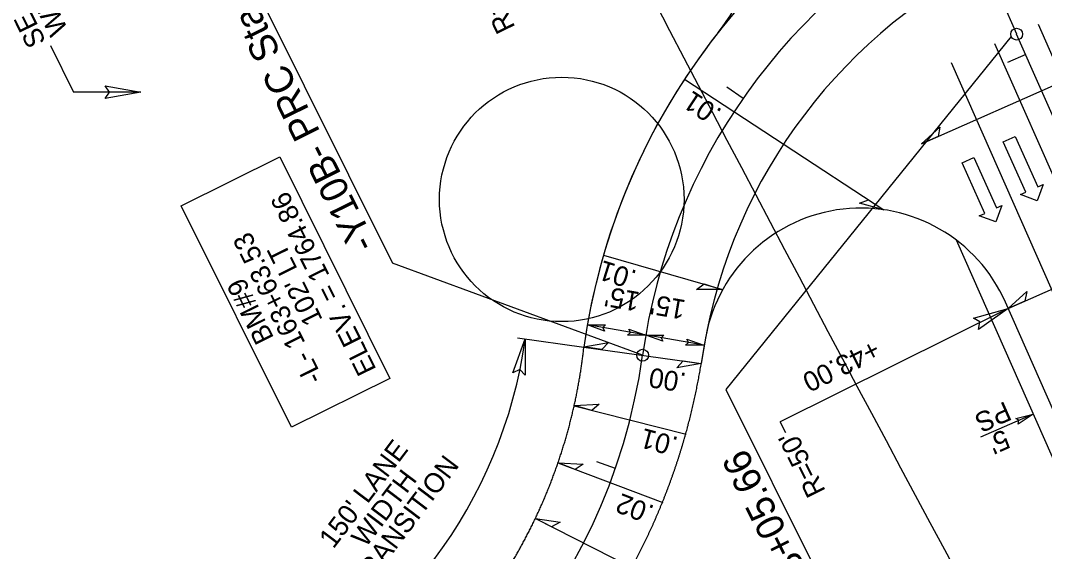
# Model space of a CAD drawing. Extents: x 472216 to 481979, y 489069 to 507339.
# Drawn here: x 475503.5 to 475762.8, y 502065.2 to 502199.7 of the extents above; entities that cross this region are included whole.
import ezdxf

# ---------------------------------------------------------------- set-up
doc = ezdxf.new("R2010")
doc.units = 0
for name, color, linetype in [('Exist Horizontal Alignment Point', 7, 'Continuous'), ('Old_Level_12', 7, 'Continuous'), ('Prop Drainage Structure Drop Inlet Grate 2 Narrow Slots and Sag Grates 840 24 CELL', 7, 'Continuous'), ('Prop Drainage Structure Drop Inlet Grate 2 Wide Slots and Sag Grates 840 22 Label', 7, 'Continuous'), ('Prop Drainage Structure Outlet Berm Ditch 850 10 CELL', 7, 'Continuous'), ('Prop Drainage Structure Pipe CSP 15in', 7, 'Continuous'), ('Prop Drainage Structure Pipe RCP 15in Class III Label', 7, 'Continuous'), ('Prop Drainage Structure Pipe RCP 24in Class III Label', 7, 'Continuous'), ('Prop Drainage Structure Pipe Side Drain 15in Label', 7, 'Continuous'), ('Prop Erosion Embankment Toe Protection CELL', 7, 'Continuous'), ('Prop Erosion Embankment Toe Protection Label', 7, 'Continuous'), ('Sheet Block Revision CELL', 7, 'Continuous'), ('Sheet North Arrow Point CELL', 7, 'Continuous'), ('Sheet PE Seal Cell', 7, 'Continuous'), ('Sheet Plot Border Outside CELL', 7, 'Continuous')]:
    doc.layers.add(name, color=color, linetype=linetype)

msp = doc.modelspace()

# ---------------------------------------------------------------- linework, layer by layer
at = {"layer": 'Exist Horizontal Alignment Point'}
msp.add_lwpolyline([(475572.15, 502096.69), (475544.25, 502152.79), (475569.16, 502165.18), (475597.06, 502109.08)], close=True, dxfattribs=at)
at = {"layer": 'Old_Level_12'}
for p, q in [((475538.53, 502257.18), (475597.67, 502138.26)), ((475754.34, 502195.64), (475682.12, 502106.24)), ((475661.02, 502114.94), (475597.67, 502138.26)), ((475682.12, 502106.24), (475733.03, 502003.86))]:
    msp.add_line(p, q, dxfattribs=at)
for centre in [(475755.71, 502196.25), (475755.71, 502196.25), (475755.71, 502196.25), (475661.02, 502114.94)]:
    msp.add_circle(centre, 1.5, dxfattribs=at)
at = {"layer": 'Prop Drainage Structure Drop Inlet Grate 2 Narrow Slots and Sag Grates 840 24 CELL'}
for points in [[(475731.6, 502168.47), (475736.28, 502172.73), (475735.83, 502170.34)], [(475722.06, 502151.79), (475715.95, 502153.41), (475718.2, 502154.33)], [(475680.96, 502131.55), (475674.64, 502131.55), (475676.57, 502133.01)], [(475753.57, 502126.8), (475758.26, 502131.05), (475757.81, 502128.67)], [(475646.17, 502117.07), (475652.41, 502118.13), (475650.74, 502116.36)], [(475675.88, 502112.88), (475669.66, 502111.73), (475671.3, 502113.52)], [(475643.71, 502102.18), (475650.02, 502102.56), (475648.17, 502100.99)], [(475639.63, 502087.73), (475645.94, 502087.4), (475643.93, 502086.04)], [(475633.87, 502073.6), (475640.12, 502072.67), (475638, 502071.51)]]:
    msp.add_lwpolyline(points, close=True, dxfattribs=at)
at = {"layer": 'Prop Drainage Structure Drop Inlet Grate 2 Wide Slots and Sag Grates 840 22 Label'}
for p, q in [((475731.6, 502168.47), (475789.07, 502193.84)), ((475671.65, 502184.87), (475722.06, 502151.79)), ((475753.57, 502126.8), (475806.17, 502150.02)), ((475651.13, 502140.29), (475681.28, 502131.55)), ((475646.16, 502117), (475675.88, 502112.88)), ((475643.69, 502102.11), (475672.01, 502094.99)), ((475639.6, 502087.67), (475666.18, 502077.67)), ((475633.87, 502073.6), (475658.26, 502061.15))]:
    msp.add_line(p, q, dxfattribs=at)
at = {"layer": 'Prop Drainage Structure Outlet Berm Ditch 850 10 CELL'}
for points in [[(475524.99, 502183.14), (475534, 502181.6), (475524.95, 502179.99), (475526.1, 502181.59)], [(475744.75, 502124.33), (475753.54, 502126.8), (475746.06, 502121.46), (475746.41, 502123.4)], [(475651.34, 502121.07), (475647.04, 502122.61), (475651.63, 502122.62), (475650.93, 502121.93)], [(475657.51, 502121.54), (475661.81, 502120), (475657.22, 502119.99), (475657.92, 502120.68)], [(475628.2, 502110.48), (475631.3, 502119.06), (475631.29, 502109.87), (475629.91, 502111.29)], [(475666.11, 502118.47), (475661.81, 502120), (475666.41, 502120.01), (475665.71, 502119.32)], [(475672.21, 502119.02), (475676.51, 502117.48), (475671.91, 502117.47), (475672.62, 502118.16)], [(475755.48, 502098.95), (475759.91, 502100.06), (475756.1, 502097.5), (475756.3, 502098.46)]]:
    msp.add_lwpolyline(points, close=True, dxfattribs=at)
at = {"layer": 'Prop Drainage Structure Pipe RCP 15in Class III Label'}
for p, q in [((476004.65, 501647.13), (475761.2, 502198.67)), ((475993.67, 501642.28), (475750.22, 502193.82))]:
    msp.add_line(p, q, dxfattribs=at)
at = {"layer": 'Prop Drainage Structure Pipe RCP 24in Class III Label'}
for p, q in [((475830.54, 501952.44), (475752.89, 502128.36)), ((475677.01, 502119.73), (475675.88, 502112.88))]:
    msp.add_line(p, q, dxfattribs=at)
for centre, radius, start, end in [((475640.96, 502227.71), 50, 321.6636, 23.3554), ((475809.6, 502094.35), 165, 141.6636, 172.1099), ((475716.29, 502112.21), 40, 23.8164, 169.165)]:
    msp.add_arc(centre, radius, start, end, dxfattribs=at)
for points in [[(475633.52, 502072.87), (475633.79, 502073.44), (475634.06, 502074), (475634.32, 502074.57), (475634.59, 502075.14), (475634.85, 502075.71), (475635.1, 502076.28), (475635.36, 502076.85), (475635.61, 502077.42), (475635.86, 502078), (475636.11, 502078.57), (475636.35, 502079.15), (475636.59, 502079.72), (475636.83, 502080.3), (475637.07, 502080.88), (475637.3, 502081.46), (475637.53, 502082.04), (475637.76, 502082.62), (475637.98, 502083.21), (475638.2, 502083.79), (475638.42, 502084.38), (475638.64, 502084.96), (475638.85, 502085.55), (475639.07, 502086.14), (475639.27, 502086.73), (475639.48, 502087.31), (475639.68, 502087.9), (475639.88, 502088.5), (475640.08, 502089.09), (475640.28, 502089.68), (475640.47, 502090.27), (475640.66, 502090.87), (475640.85, 502091.46), (475641.03, 502092.06), (475641.21, 502092.66), (475641.39, 502093.25), (475641.56, 502093.85), (475641.74, 502094.45), (475641.91, 502095.05), (475642.07, 502095.65), (475642.24, 502096.25), (475642.4, 502096.85), (475642.56, 502097.46), (475642.72, 502098.06), (475642.87, 502098.66), (475643.02, 502099.27), (475643.17, 502099.87), (475643.31, 502100.48), (475643.46, 502101.08), (475643.59, 502101.69), (475643.73, 502102.3), (475643.86, 502102.9), (475644, 502103.51), (475644.12, 502104.12), (475644.25, 502104.73), (475644.37, 502105.34), (475644.49, 502105.95), (475644.61, 502106.56), (475644.72, 502107.17), (475644.83, 502107.78), (475644.94, 502108.39), (475645.05, 502109.01), (475645.15, 502109.62), (475645.25, 502110.23), (475645.35, 502110.85), (475645.44, 502111.46), (475645.53, 502112.07), (475645.62, 502112.69), (475645.71, 502113.3), (475645.79, 502113.92), (475645.87, 502114.53), (475645.95, 502115.15), (475646.02, 502115.77), (475646.16, 502117)], [(475657.8, 502060.31), (475658.16, 502060.97), (475658.51, 502061.63), (475658.87, 502062.29), (475659.22, 502062.96), (475659.57, 502063.63), (475659.91, 502064.3), (475660.25, 502064.97), (475660.59, 502065.64), (475660.93, 502066.31), (475661.26, 502066.99), (475661.59, 502067.66), (475661.92, 502068.34), (475662.24, 502069.02), (475662.56, 502069.7), (475662.88, 502070.38), (475663.19, 502071.07), (475663.5, 502071.76), (475663.81, 502072.44), (475664.12, 502073.13), (475664.42, 502073.82), (475664.72, 502074.51), (475665.01, 502075.21), (475665.3, 502075.9), (475665.59, 502076.6), (475665.88, 502077.3), (475666.16, 502077.99), (475666.44, 502078.7), (475666.72, 502079.4), (475666.99, 502080.1), (475667.26, 502080.8), (475667.53, 502081.51), (475667.79, 502082.22), (475668.05, 502082.93), (475668.31, 502083.63), (475668.56, 502084.35), (475668.81, 502085.06), (475669.06, 502085.77), (475669.3, 502086.48), (475669.54, 502087.2), (475669.78, 502087.92), (475670.02, 502088.64), (475670.25, 502089.35), (475670.47, 502090.07), (475670.7, 502090.8), (475670.92, 502091.52), (475671.14, 502092.24), (475671.35, 502092.97), (475671.56, 502093.69), (475671.77, 502094.42), (475671.98, 502095.15), (475672.18, 502095.88), (475672.37, 502096.6), (475672.57, 502097.34), (475672.76, 502098.07), (475672.95, 502098.8), (475673.13, 502099.53), (475673.31, 502100.27), (475673.49, 502101), (475673.67, 502101.74), (475673.84, 502102.48), (475674.01, 502103.21), (475674.17, 502103.95), (475674.33, 502104.69), (475674.49, 502105.43), (475674.64, 502106.18), (475674.79, 502106.92), (475674.94, 502107.66), (475675.09, 502108.4), (475675.23, 502109.15), (475675.36, 502109.89), (475675.5, 502110.64), (475675.63, 502111.39), (475675.88, 502112.88)], [(475606.62, 502035.12), (475607.07, 502035.57), (475607.52, 502036.02), (475607.96, 502036.47), (475608.4, 502036.92), (475608.84, 502037.38), (475609.28, 502037.83), (475609.71, 502038.29), (475610.14, 502038.75), (475610.57, 502039.21), (475611, 502039.68), (475611.43, 502040.14), (475611.85, 502040.61), (475612.28, 502041.08), (475612.69, 502041.55), (475613.11, 502042.03), (475613.53, 502042.5), (475613.94, 502042.98), (475614.35, 502043.46), (475614.76, 502043.94), (475615.16, 502044.42), (475615.57, 502044.91), (475615.97, 502045.39), (475616.37, 502045.88), (475616.77, 502046.37), (475617.16, 502046.86), (475617.55, 502047.36), (475617.94, 502047.85), (475618.33, 502048.35), (475618.72, 502048.85), (475619.1, 502049.35), (475619.48, 502049.85), (475619.86, 502050.35), (475620.23, 502050.86), (475620.61, 502051.37), (475620.98, 502051.87), (475621.35, 502052.38), (475621.71, 502052.9), (475622.08, 502053.41), (475622.44, 502053.93), (475622.8, 502054.44), (475623.15, 502054.96), (475623.51, 502055.48), (475623.86, 502056), (475624.21, 502056.52), (475624.56, 502057.05), (475624.9, 502057.57), (475625.24, 502058.1), (475625.58, 502058.63), (475625.92, 502059.16), (475626.25, 502059.69), (475626.59, 502060.23), (475626.92, 502060.76), (475627.24, 502061.3), (475627.57, 502061.84), (475627.89, 502062.37), (475628.21, 502062.92), (475628.53, 502063.46), (475628.84, 502064), (475629.15, 502064.55), (475629.46, 502065.09), (475629.77, 502065.64), (475630.07, 502066.19), (475630.37, 502066.74), (475630.67, 502067.29), (475630.97, 502067.84), (475631.26, 502068.4), (475631.55, 502068.95), (475631.84, 502069.51), (475632.13, 502070.06), (475632.41, 502070.62), (475632.69, 502071.18), (475632.97, 502071.75), (475633.25, 502072.31), (475633.52, 502072.87)]]:
    msp.add_spline(points, degree=3, dxfattribs=at)
at = {"layer": 'Prop Drainage Structure Pipe Side Drain 15in Label'}
for p, q in [((475752.32, 502168.99), (475755.32, 502170.35)), ((475758.07, 502156.23), (475752.32, 502168.99)), ((475755.32, 502170.35), (475761.08, 502157.58)), ((475741.88, 502163.64), (475744.88, 502164.99)), ((475747.63, 502150.87), (475741.88, 502163.64)), ((475744.88, 502164.99), (475750.64, 502152.23)), ((475762.44, 502158.2), (475760.91, 502154.06)), ((475761.08, 502157.58), (475762.44, 502158.2)), ((475756.7, 502155.61), (475758.07, 502156.23)), ((475760.91, 502154.06), (475756.7, 502155.61)), ((475752, 502152.85), (475750.47, 502148.7)), ((475750.64, 502152.23), (475752, 502152.85)), ((475746.26, 502150.26), (475747.63, 502150.87)), ((475750.47, 502148.7), (475746.26, 502150.26))]:
    msp.add_line(p, q, dxfattribs=at)
at = {"layer": 'Prop Erosion Embankment Toe Protection CELL'}
msp.add_line((475829.51, 501942.39), (475740.49, 502144.06), dxfattribs=at)
at = {"layer": 'Prop Erosion Embankment Toe Protection Label'}
for p, q in [((475982.69, 501637.44), (475739.25, 502188.98)), ((475697.29, 502095.27), (475695.88, 502098.11))]:
    msp.add_line(p, q, dxfattribs=at)
at = {"layer": 'Sheet Block Revision CELL'}
for p, q in [((475511.1, 502193.41), (475517, 502181.55)), ((475753.57, 502126.8), (475695.88, 502098.11)), ((475676.59, 502117.47), (475647.04, 502122.61)), ((475629.32, 502119.34), (475646.16, 502117)), ((475759.91, 502100.06), (475746.6, 502094.18))]:
    msp.add_line(p, q, dxfattribs=at)
for centre, radius, start, end in [((475531.22, 499936.6), 2245, 89.92928, 90.3631), ((475512.44, 502135.53), 120, 293.6967, 352.1099)]:
    msp.add_arc(centre, radius, start, end, dxfattribs=at)
at = {"layer": 'Sheet North Arrow Point CELL'}
msp.add_line((475999.16, 501644.71), (475755.71, 502196.25), dxfattribs=at)
for centre, radius, start, end in [((473624.13, 501255.38), 2330, 23.81642, 43.37358), ((486928.47, 508069.92), 12700, 206.801639, 209.062037), ((475809.6, 502094.35), 150, 117.0301, 172.1099), ((475512.44, 502135.53), 150, 214.8879, 352.1099)]:
    msp.add_arc(centre, radius, start, end, dxfattribs=at)
at = {"layer": 'Sheet PE Seal Cell'}
for p, q in [((475758, 502191.07), (475753.42, 502189.05)), ((475686.45, 502179.99), (475682.35, 502182.85)), ((475654.13, 502086.3), (475649.41, 502087.94))]:
    msp.add_line(p, q, dxfattribs=at)
at = {"layer": 'Sheet Plot Border Outside CELL'}
msp.add_circle((475640.56, 502154.4), 30.95, dxfattribs=at)
for radius in [165, 135]:
    msp.add_arc((475809.6, 502094.35), radius, 117.0301, 172.1099, dxfattribs=at)

# ---------------------------------------------------------------- texts
at = {"layer": 'Old_Level_12'}
for s, p in [('-Y10B- PRC Sta.  18+29.51', (475593.65, 502143.08)), ('-L- PC Sta.  163+05.66', (475729.91, 502005.68))]:
    msp.add_text(s, height=7, rotation=116.4407, dxfattribs=at).set_placement(p)
at = {"layer": 'Prop Drainage Structure Drop Inlet Grate 2 Narrow Slots and Sag Grates 840 24 CELL'}
for s, rotation, p in [('.01', 146.7279, (475681.38, 502176.99)), ('.01', 162.6502, (475659.84, 502136.26)), ('.00', 170.9279, (475672.29, 502110.37)), ('.01', 165.0643, (475670.3, 502094.11)), ('.02', 158.5602, (475664.26, 502076.7))]:
    msp.add_text(s, height=5, rotation=rotation, dxfattribs=at).set_placement(p)
at = {"layer": 'Prop Drainage Structure Pipe CSP 15in'}
for s, rotation, p in [('WELL', 116.4407, (475515.66, 502197.41)), ('SEAL ', 116.4407, (475510.09, 502194.38)), ("R=50'", 116.4407, (475628.86, 502198)), ('ELEV. = 1764.86', 116.4407, (475593.71, 502111.37)), ('-L- 163+63.53', 116.4407, (475580.21, 502109.09)), ("102' LT", 116.4407, (475580.14, 502123.94)), ('BM#9', 116.4407, (475567.8, 502119.31)), ("15'", 170.1339, (475660.53, 502130.87)), ("15'", 170.1339, (475672.16, 502128.84)), ('+43.00', 206.4407, (475719.51, 502119.07)), ('PS', 203.8164, (475752.83, 502103.37)), ("5'", 203.8164, (475752.51, 502096.3)), ("150' LANE ", 52.9044, (475582.75, 502065.73)), ("R=50'", 116.4407, (475707.44, 502080.57)), ('TRANSITION', 52.9044, (475590.37, 502054.79)), ('WIDTH ', 52.9044, (475590.92, 502066.02))]:
    msp.add_text(s, height=5, rotation=rotation, dxfattribs=at).set_placement(p)

doc.saveas('drawing.dxf')
